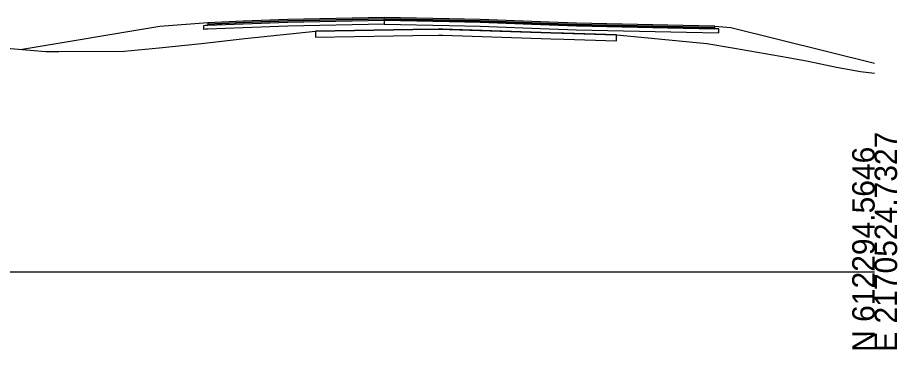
# Model space of a CAD drawing. Extents: x -26 to 1303, y -3010 to 12038.
# Drawn here: x 193 to 302.8, y 10490.3 to 10531.7 of the extents above; entities that cross this region are included whole.
import ezdxf

# ---------------------------------------------------------------- set-up
doc = ezdxf.new("R2010")
doc.units = 0
for name, color, linetype in [('RD_GPK_XS_Cell', 7, 'Continuous'), ('RD_XS_Base', 7, 'Continuous'), ('RD_XS_ExGround', 7, 'Continuous'), ('RD_XS_ExPaveRet', 7, 'Continuous'), ('RD_XS_Greenside', 7, 'Continuous'), ('RD_XS_Pave', 7, 'Continuous'), ('RD_XS_PaveOvlay_CP', 7, 'Continuous'), ('RD_XS_TieSlope', 7, 'Continuous')]:
    doc.layers.add(name, color=color, linetype=linetype)

msp = doc.modelspace()

# ---------------------------------------------------------------- linework, layer by layer
at = {"layer": 'RD_GPK_XS_Cell'}
msp.add_line((150, 10500), (300, 10500), dxfattribs=at)
at = {"layer": 'RD_XS_Base'}
for p, q in [((238.77, 10531.46), (238.77, 10531.57)), ((238.77, 10531.57), (238.77, 10531.14)), ((216.27, 10530.75), (216.49, 10530.76)), ((216.27, 10530.48), (216.27, 10530.75)), ((216.27, 10530.25), (216.27, 10530.48)), ((216.49, 10530.76), (216.77, 10530.77)), ((216.77, 10530.77), (221.19, 10530.94)), ((221.19, 10530.44), (216.77, 10530.27)), ((221.19, 10530.94), (226.77, 10531.17)), ((226.77, 10530.67), (221.19, 10530.44)), ((226.77, 10531.17), (238.77, 10531.41)), ((238.77, 10530.91), (226.77, 10530.67)), ((238.77, 10531.41), (238.77, 10531.46)), ((238.77, 10531.41), (238.77, 10531.41)), ((246.91, 10531.24), (238.77, 10531.41)), ((238.77, 10531.41), (238.77, 10531.41)), ((238.77, 10531.41), (238.77, 10531.08)), ((238.77, 10531.14), (238.77, 10530.91)), ((238.77, 10531.08), (238.77, 10530.91)), ((238.77, 10530.91), (246.91, 10530.74)), ((250.77, 10531.17), (246.91, 10531.24)), ((246.91, 10530.74), (250.77, 10530.67)), ((259.39, 10530.82), (250.77, 10531.17)), ((250.77, 10530.67), (259.39, 10530.32)), ((262.77, 10530.69), (259.39, 10530.82)), ((276.12, 10530.42), (262.77, 10530.69)), ((216.49, 10530.26), (216.27, 10530.25)), ((216.77, 10530.27), (216.49, 10530.26)), ((259.39, 10530.32), (262.77, 10530.19)), ((262.77, 10530.19), (276.53, 10529.91)), ((280.07, 10530.34), (276.12, 10530.42)), ((276.53, 10529.91), (280.57, 10529.83)), ((280.46, 10530.34), (280.07, 10530.34)), ((280.57, 10530.33), (280.46, 10530.34)), ((280.57, 10529.94), (280.57, 10530.33)), ((280.57, 10529.83), (280.57, 10529.94))]:
    msp.add_line(p, q, dxfattribs=at)
at = {"layer": 'RD_XS_ExGround'}
msp.add_lwpolyline([(190.66, 10527.98), (196.54, 10527.51), (198.18, 10527.5), (206.33, 10527.52), (210.7, 10527.96), (215.97, 10528.5), (221.4, 10529.11), (230.23, 10530.02), (242.35, 10530.24), (245.69, 10530.3), (259.59, 10529.84), (267.8, 10529.57), (269.98, 10529.36), (279.07, 10528.5), (282.51, 10527.89), (289.19, 10526.74), (291.7, 10526.28), (295.24, 10525.52), (298.24, 10524.99), (300, 10524.8)], dxfattribs=at)
at = {"layer": 'RD_XS_ExPaveRet'}
for p, q in [((245.69, 10530.3), (245.58, 10530.3)), ((261.2, 10529.78), (259.59, 10529.84)), ((267.8, 10529.57), (261.2, 10529.78))]:
    msp.add_line(p, q, dxfattribs=at)
for points in [[(259.59, 10529.84), (246.1, 10530.29), (245.69, 10530.3), (245.58, 10530.3), (242.35, 10530.24), (239.93, 10530.19), (230.23, 10530.02), (230.23, 10529.87), (230.23, 10529.27), (239.93, 10529.44), (242.35, 10529.49), (245.58, 10529.55), (245.69, 10529.55), (246.1, 10529.54), (259.59, 10529.09), (261.2, 10529.03), (267.8, 10528.82), (267.8, 10529.53), (267.8, 10529.57), (261.2, 10529.78), (259.59, 10529.84)], [(245.58, 10530.3), (242.35, 10530.24), (239.93, 10530.19), (230.23, 10530.02), (230.23, 10529.87), (230.23, 10529.27), (239.93, 10529.44), (242.35, 10529.49), (245.58, 10529.55), (245.69, 10529.55), (246.1, 10529.54), (259.59, 10529.09), (261.2, 10529.03), (267.8, 10528.82), (267.8, 10529.53), (267.8, 10529.57)], [(259.59, 10529.84), (246.1, 10530.29), (245.69, 10530.3)]]:
    msp.add_lwpolyline(points, dxfattribs=at)
at = {"layer": 'RD_XS_Greenside'}
for p, q in [((210.77, 10530.6), (193.61, 10527.74)), ((282.07, 10530.5), (300, 10526.02))]:
    msp.add_line(p, q, dxfattribs=at)
at = {"layer": 'RD_XS_Pave'}
for p, q in [((238.77, 10531.73), (226.77, 10531.48)), ((238.77, 10531.57), (226.77, 10531.33)), ((226.77, 10531.33), (238.77, 10531.57)), ((246.91, 10531.56), (238.77, 10531.73)), ((238.77, 10531.46), (238.77, 10531.57)), ((238.77, 10531.57), (246.91, 10531.4)), ((246.91, 10531.4), (238.77, 10531.57)), ((238.77, 10531.57), (238.77, 10531.57)), ((238.77, 10531.57), (238.77, 10531.57)), ((238.77, 10531.57), (238.77, 10531.46)), ((250.77, 10531.49), (246.91, 10531.56)), ((221.19, 10531.26), (216.77, 10531.08)), ((221.19, 10531.1), (216.77, 10530.92)), ((216.77, 10530.92), (221.19, 10531.1)), ((216.77, 10531.08), (216.77, 10531)), ((216.77, 10531), (216.77, 10530.92)), ((216.77, 10530.77), (221.19, 10530.94)), ((216.77, 10530.92), (216.77, 10530.84)), ((216.77, 10530.84), (216.77, 10530.77)), ((226.77, 10531.48), (221.19, 10531.26)), ((226.77, 10531.33), (221.19, 10531.1)), ((221.19, 10531.1), (226.77, 10531.33)), ((221.19, 10530.94), (226.77, 10531.17)), ((226.77, 10531.17), (238.77, 10531.41)), ((238.77, 10531.41), (238.77, 10531.46)), ((238.77, 10531.46), (238.77, 10531.41)), ((238.77, 10531.41), (238.77, 10531.41)), ((238.77, 10531.41), (238.77, 10531.41)), ((238.77, 10531.41), (246.91, 10531.24)), ((246.91, 10531.4), (250.77, 10531.33)), ((250.77, 10531.33), (246.91, 10531.4)), ((246.91, 10531.24), (250.77, 10531.17)), ((259.39, 10531.14), (250.77, 10531.49)), ((250.77, 10531.33), (259.39, 10530.98)), ((259.39, 10530.98), (250.77, 10531.33)), ((250.77, 10531.17), (259.39, 10530.82)), ((262.77, 10531.01), (259.39, 10531.14)), ((259.39, 10530.98), (262.77, 10530.85)), ((262.77, 10530.85), (259.39, 10530.98)), ((259.39, 10530.82), (262.77, 10530.69)), ((276.12, 10530.74), (262.77, 10531.01)), ((262.77, 10530.85), (276.12, 10530.58)), ((276.12, 10530.58), (262.77, 10530.85)), ((262.77, 10530.69), (276.12, 10530.42)), ((280.07, 10530.66), (276.12, 10530.74)), ((276.12, 10530.58), (280.07, 10530.5)), ((280.07, 10530.5), (276.12, 10530.58)), ((280.07, 10530.54), (280.07, 10530.66)), ((280.07, 10530.5), (280.07, 10530.54)), ((280.07, 10530.38), (280.07, 10530.5)), ((276.12, 10530.42), (280.07, 10530.34)), ((280.07, 10530.34), (280.07, 10530.38))]:
    msp.add_line(p, q, dxfattribs=at)
at = {"layer": 'RD_XS_PaveOvlay_CP'}
for p, q in [((238.77, 10531.73), (226.77, 10531.48)), ((246.91, 10531.56), (238.77, 10531.73)), ((250.77, 10531.49), (246.91, 10531.56)), ((221.19, 10531.26), (216.77, 10531.08)), ((226.77, 10531.48), (221.19, 10531.26)), ((259.39, 10531.14), (250.77, 10531.49)), ((262.77, 10531.01), (259.39, 10531.14)), ((276.12, 10530.74), (262.77, 10531.01)), ((280.07, 10530.66), (276.12, 10530.74))]:
    msp.add_line(p, q, dxfattribs=at)
at = {"layer": 'RD_XS_TieSlope'}
for p, q in [((216.77, 10531.08), (210.77, 10530.6)), ((280.07, 10530.66), (282.07, 10530.5))]:
    msp.add_line(p, q, dxfattribs=at)

# ---------------------------------------------------------------- texts
at = {"layer": 'RD_GPK_XS_Cell'}
for s, p in [('E 2170524.7327', (302.8, 10490)), ('N 612294.5646', (300, 10490))]:
    msp.add_text(s, height=2.8, rotation=90, dxfattribs=at).set_placement(p)

doc.saveas('drawing.dxf')
